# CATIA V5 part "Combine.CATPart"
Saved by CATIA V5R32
Part number: Part1
Bounding box of the stored display mesh (mm): x 0 to 48.303, y -48.737 to 82.157, z 0 to 68.503
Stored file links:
  D:\PROJECTS\Project 2022\CATIA V5 6R 2022\Resources\Part Files\c17_catia_v6_6r2022_prt\Combine.CATPart
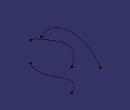
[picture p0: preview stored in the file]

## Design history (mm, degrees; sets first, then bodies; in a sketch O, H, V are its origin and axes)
Set1
  Sketch1 on xy-plane, origin (0, 0, 0), H (1, 0, 0), V (0, 1, 0)
    spline S1 through (48.3033, 66.5608) (25.8768, 40.109) (39.1026, 7.9068) (36.515, -36.6587)
  Sketch2 on yz-plane, origin (0, 0, 0), H (0, 1, 0), V (0, 0, 1)
    arc A1 centre (18.404, -5.761) radius 74.2849 from (-48.7369, 26.0251) to (82.1569, 32.368) cw
  Combine1: Curve1 Sketch2, Curve2 Sketch1
Body1 (main body)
